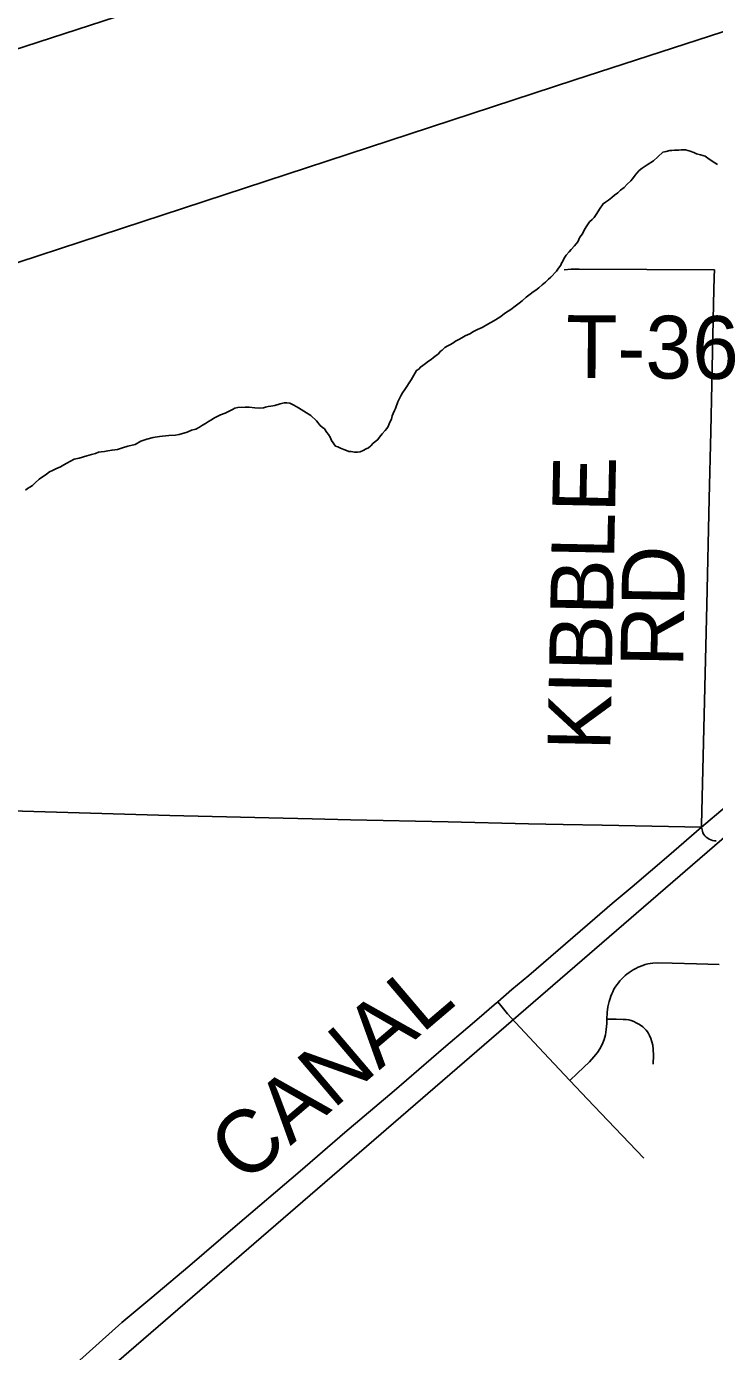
# Model space of a CAD drawing. Extents: x 2.1 to 73.9, y 4 to 26.
# Drawn here: x 47.83 to 48.141, y 21.81 to 22.409 of the extents above; entities that cross this region are included whole.
import ezdxf

# ---------------------------------------------------------------- set-up
doc = ezdxf.new("R2010")
doc.units = 0
for name, color, linetype in [('GM_X_City_Street', 7, 'Continuous'), ('GM_X_County_Road', 7, 'Continuous'), ('GM_X_County_Road_Text', 7, 'Continuous'), ('GM_X_Minor_River', 7, 'Continuous'), ('GM_X_Rail_Line', 7, 'Continuous'), ('GM_X_Township_Road', 7, 'Continuous'), ('GM_X_Township_Road_Text', 7, 'Continuous')]:
    doc.layers.add(name, color=color, linetype=linetype)

msp = doc.modelspace()

# ---------------------------------------------------------------- linework, layer by layer
at = {"layer": 'GM_X_City_Street'}
for points in [[(47.74205, 22.37111), (48.0048, 22.45661)], [(48.13542, 22.04657), (48.13576, 22.04481), (48.13601, 22.04404), (48.1364, 22.04327), (48.13689, 22.04256), (48.13719, 22.04227), (48.13752, 22.042), (48.13825, 22.04153), (48.13888, 22.04116), (48.13965, 22.04082), (48.14038, 22.04057), (48.1412, 22.0404), (48.14201, 22.04033)], [(48.07589, 21.93204), (48.0793, 21.93531), (48.08468, 21.94046), (48.08677, 21.94271), (48.08829, 21.94462), (48.08946, 21.94641), (48.09044, 21.9483), (48.09135, 21.95056), (48.09192, 21.95261), (48.09234, 21.95501), (48.09256, 21.95776), (48.09264, 21.95971), (48.09276, 21.96275), (48.09308, 21.96526), (48.09362, 21.96772), (48.09403, 21.96909), (48.09438, 21.97014), (48.09482, 21.9712), (48.09529, 21.97217), (48.09579, 21.97326), (48.09632, 21.97416), (48.09708, 21.97523), (48.09782, 21.9762), (48.09851, 21.97703), (48.09928, 21.97786), (48.09992, 21.97856), (48.10087, 21.97942), (48.10166, 21.98009), (48.10261, 21.9808), (48.10351, 21.98145), (48.10443, 21.98208), (48.10566, 21.98273), (48.10669, 21.98322), (48.10878, 21.98401), (48.10996, 21.9844), (48.11109, 21.98472), (48.1122, 21.98493), (48.1134, 21.98509), (48.11531, 21.98523), (48.12217, 21.98512), (48.13305, 21.98477), (48.1433, 21.98449)], [(48.10928, 21.89691), (48.09626, 21.91065), (48.08381, 21.92365), (48.07589, 21.93204), (48.06634, 21.94215), (48.05975, 21.94915), (48.05135, 21.9582), (48.04765, 21.96223), (48.04522, 21.96519), (48.04326, 21.96757)], [(48.11349, 21.93936), (48.11362, 21.94352), (48.11353, 21.946), (48.1133, 21.94794), (48.11298, 21.94957), (48.11253, 21.95097), (48.1119, 21.95232), (48.11142, 21.95325), (48.1109, 21.954), (48.11029, 21.95476), (48.10962, 21.95551), (48.10883, 21.95624), (48.10786, 21.95697), (48.107, 21.95755), (48.10588, 21.95816), (48.10475, 21.95871), (48.10365, 21.95913), (48.1025, 21.95944), (48.10127, 21.95957), (48.09995, 21.95966), (48.09687, 21.95968), (48.09264, 21.95971)]]:
    msp.add_lwpolyline(points, dxfattribs=at)
at = {"layer": 'GM_X_County_Road'}
for points in [[(48.13542, 22.04657), (48.14601, 22.05566)], [(48.04326, 21.96757), (48.04968, 21.97313), (48.05726, 21.97957), (48.08718, 22.00533), (48.09498, 22.01201), (48.10402, 22.01961), (48.12054, 22.03378), (48.13542, 22.04657)], [(47.85274, 21.8043), (47.87325, 21.82265), (47.88596, 21.83313), (47.90403, 21.84836), (47.92456, 21.86597), (47.95388, 21.89102), (47.97417, 21.90845), (47.9964, 21.92743), (48.0188, 21.94668), (48.02977, 21.95593), (48.03482, 21.96037), (48.04169, 21.96621), (48.04326, 21.96757)]]:
    msp.add_lwpolyline(points, dxfattribs=at)
at = {"layer": 'GM_X_Minor_River'}
for points in [[(47.80764, 21.75007), (48.75069, 22.56484)], [(48.12925, 22.35249), (48.12811, 22.35271), (48.12621, 22.35276), (48.12507, 22.3526), (48.12412, 22.35262), (48.12317, 22.35265), (48.12203, 22.35248), (48.12108, 22.35251), (48.11936, 22.35198), (48.11783, 22.35164), (48.11569, 22.34961), (48.11374, 22.34776), (48.11085, 22.34593), (48.10853, 22.34447), (48.10718, 22.34337), (48.1062, 22.34225), (48.10542, 22.34132), (48.10424, 22.33964), (48.10345, 22.33871), (48.10171, 22.33724), (48.10034, 22.33575), (48.09879, 22.33446), (48.09762, 22.33335), (48.09607, 22.33225), (48.09491, 22.33114), (48.09336, 22.33004), (48.09201, 22.32913), (48.09085, 22.3284), (48.08927, 22.32597), (48.08808, 22.32391), (48.08689, 22.32223), (48.08592, 22.3213), (48.08476, 22.32019), (48.08318, 22.31796), (48.08238, 22.31646), (48.08158, 22.31477), (48.0804, 22.31328), (48.0794, 22.31121), (48.07803, 22.30935), (48.07647, 22.30768), (48.07549, 22.30657), (48.07412, 22.30508), (48.07333, 22.30377), (48.07273, 22.30246), (48.07213, 22.30152), (48.07173, 22.30058), (48.07075, 22.29928), (48.06976, 22.29797), (48.06723, 22.29519), (48.06625, 22.29427), (48.06489, 22.29297), (48.06334, 22.29168), (48.06179, 22.29039), (48.06043, 22.28928), (48.05927, 22.28855), (48.05792, 22.28745), (48.05617, 22.28616), (48.05423, 22.2845), (48.05288, 22.2834), (48.05113, 22.28211), (48.0492, 22.28064), (48.04669, 22.279), (48.04417, 22.27716), (48.04147, 22.27552), (48.03877, 22.27388), (48.03627, 22.27242), (48.03416, 22.27153), (48.03223, 22.27063), (48.03069, 22.26953), (48.02858, 22.26863), (48.02703, 22.26772), (48.02569, 22.267), (48.02415, 22.26627), (48.02299, 22.26535), (48.02164, 22.26463), (48.02067, 22.26408), (48.01933, 22.26336), (48.01816, 22.26225), (48.01719, 22.26151), (48.01641, 22.26058), (48.01544, 22.25985), (48.01428, 22.25893), (48.01312, 22.25801), (48.01196, 22.25728), (48.0106, 22.25617), (48.00944, 22.25525), (48.00828, 22.25452), (48.0075, 22.25359), (48.00653, 22.25305), (48.00415, 22.24874), (48.00316, 22.24743), (48.00217, 22.24575), (48.00119, 22.24445), (48.0002, 22.24295), (47.99961, 22.24183), (47.99881, 22.24033), (47.99801, 22.23883), (47.9978, 22.23789), (47.99739, 22.23676), (47.99699, 22.23582), (47.99658, 22.23488)], [(48.14257, 22.34608), (48.14014, 22.34766), (48.13828, 22.34903), (48.13697, 22.34983), (48.13489, 22.35045), (48.13319, 22.35087), (48.13188, 22.35148), (48.13019, 22.35209), (48.12925, 22.35249)], [(47.99658, 22.23488), (47.99598, 22.23356), (47.99557, 22.23243), (47.99516, 22.23092), (47.99456, 22.22999), (47.99415, 22.22886), (47.99374, 22.22773), (47.99315, 22.2268), (47.99237, 22.22587), (47.991, 22.22438), (47.98983, 22.22289), (47.98904, 22.22177), (47.98807, 22.22104), (47.98691, 22.22012), (47.98593, 22.219), (47.98477, 22.21808), (47.9838, 22.21754), (47.98246, 22.21681), (47.98111, 22.21628), (47.97978, 22.21612), (47.97845, 22.21615), (47.97694, 22.21638), (47.97599, 22.21641), (47.97486, 22.21682), (47.97373, 22.21722), (47.97223, 22.21783), (47.97091, 22.21843), (47.96997, 22.21884), (47.96814, 22.22135), (47.96741, 22.22289), (47.96668, 22.22405), (47.96595, 22.22502), (47.96485, 22.22656), (47.96392, 22.22735), (47.96299, 22.22813), (47.96133, 22.23026), (47.95873, 22.23261), (47.95555, 22.23459), (47.95312, 22.23617), (47.95106, 22.23736), (47.94918, 22.23817), (47.94786, 22.23839), (47.94672, 22.23842), (47.94481, 22.2379), (47.94251, 22.2372), (47.9406, 22.23686), (47.93946, 22.2367), (47.93831, 22.23635), (47.93736, 22.23619), (47.93564, 22.23604), (47.93337, 22.2361), (47.9309, 22.23635), (47.92901, 22.2364), (47.92577, 22.23629), (47.92444, 22.23594), (47.92328, 22.2354), (47.92175, 22.23468), (47.92001, 22.23378), (47.9179, 22.23288), (47.91637, 22.23216), (47.91521, 22.23162), (47.91348, 22.23052), (47.91251, 22.22998), (47.91116, 22.22906), (47.90981, 22.22834), (47.90846, 22.22742), (47.90673, 22.22652), (47.90482, 22.226), (47.90289, 22.22509), (47.89926, 22.22405), (47.89754, 22.22371), (47.8945, 22.2236), (47.89031, 22.22314), (47.88745, 22.22264), (47.88458, 22.22195), (47.8819, 22.22107), (47.87939, 22.21961), (47.87595, 22.21875), (47.87366, 22.21805), (47.87136, 22.21735), (47.86888, 22.21703), (47.86698, 22.2167), (47.86545, 22.21636), (47.86393, 22.21621), (47.86278, 22.21605), (47.86144, 22.21551), (47.85953, 22.21499), (47.85742, 22.21447), (47.85398, 22.21342), (47.85169, 22.21291), (47.85014, 22.212), (47.84841, 22.21109), (47.84707, 22.21037), (47.84552, 22.20946), (47.84341, 22.20856), (47.84187, 22.20784), (47.84053, 22.20711), (47.83917, 22.2062), (47.83589, 22.20381), (47.83413, 22.20215), (47.83297, 22.20104)], [(47.83297, 22.20104), (47.83162, 22.20031), (47.83065, 22.19958), (47.82968, 22.19884)]]:
    msp.add_lwpolyline(points, dxfattribs=at)
at = {"layer": 'GM_X_Rail_Line'}
msp.add_lwpolyline([(46.37711, 21.82964), (47.12758, 22.0728), (48.07818, 22.38437), (48.43367, 22.49981), (48.47937, 22.5158), (48.52401, 22.53278), (48.5733, 22.55674), (48.61543, 22.57739), (48.65067, 22.59609), (48.67554, 22.61161), (48.7021, 22.62796), (48.72324, 22.64236), (48.75853, 22.66792)], dxfattribs=at)
at = {"layer": 'GM_X_Township_Road'}
for points in [[(48.07333, 22.29846), (48.07652, 22.29879), (48.08008, 22.29887), (48.1412, 22.29853)], [(48.13542, 22.04657), (48.13545, 22.04761), (48.13779, 22.1471), (48.13888, 22.19495), (48.13958, 22.2254), (48.14003, 22.24684), (48.14079, 22.28319), (48.14111, 22.29531), (48.1412, 22.29853)], [(47.63245, 22.05838), (47.63467, 22.05837), (47.64026, 22.05834), (47.66667, 22.05769), (47.68407, 22.05723), (47.70271, 22.05672), (47.73409, 22.05596), (47.78723, 22.05475), (47.80525, 22.05435), (47.82327, 22.05389), (47.89504, 22.05189), (47.93978, 22.0508), (47.95935, 22.05029), (47.97675, 22.04993), (48.02087, 22.0489), (48.05723, 22.04811), (48.07277, 22.04777), (48.09048, 22.04741), (48.13542, 22.04657)]]:
    msp.add_lwpolyline(points, dxfattribs=at)

# ---------------------------------------------------------------- texts
at = {"layer": 'GM_X_County_Road_Text'}
msp.add_text('CANAL', height=0.028409, rotation=40.38749, dxfattribs=at).set_placement((47.92856, 21.88454))
at = {"layer": 'GM_X_Township_Road_Text'}
for s, rotation, p in [('T-36', 359.64418, (48.07407, 22.24962)), ('KIBBLE', 88.85775, (48.09413, 22.08094)), ('RD', 89.01275, (48.12711, 22.11874))]:
    msp.add_text(s, height=0.028409, rotation=rotation, dxfattribs=at).set_placement(p)

doc.saveas('drawing.dxf')
